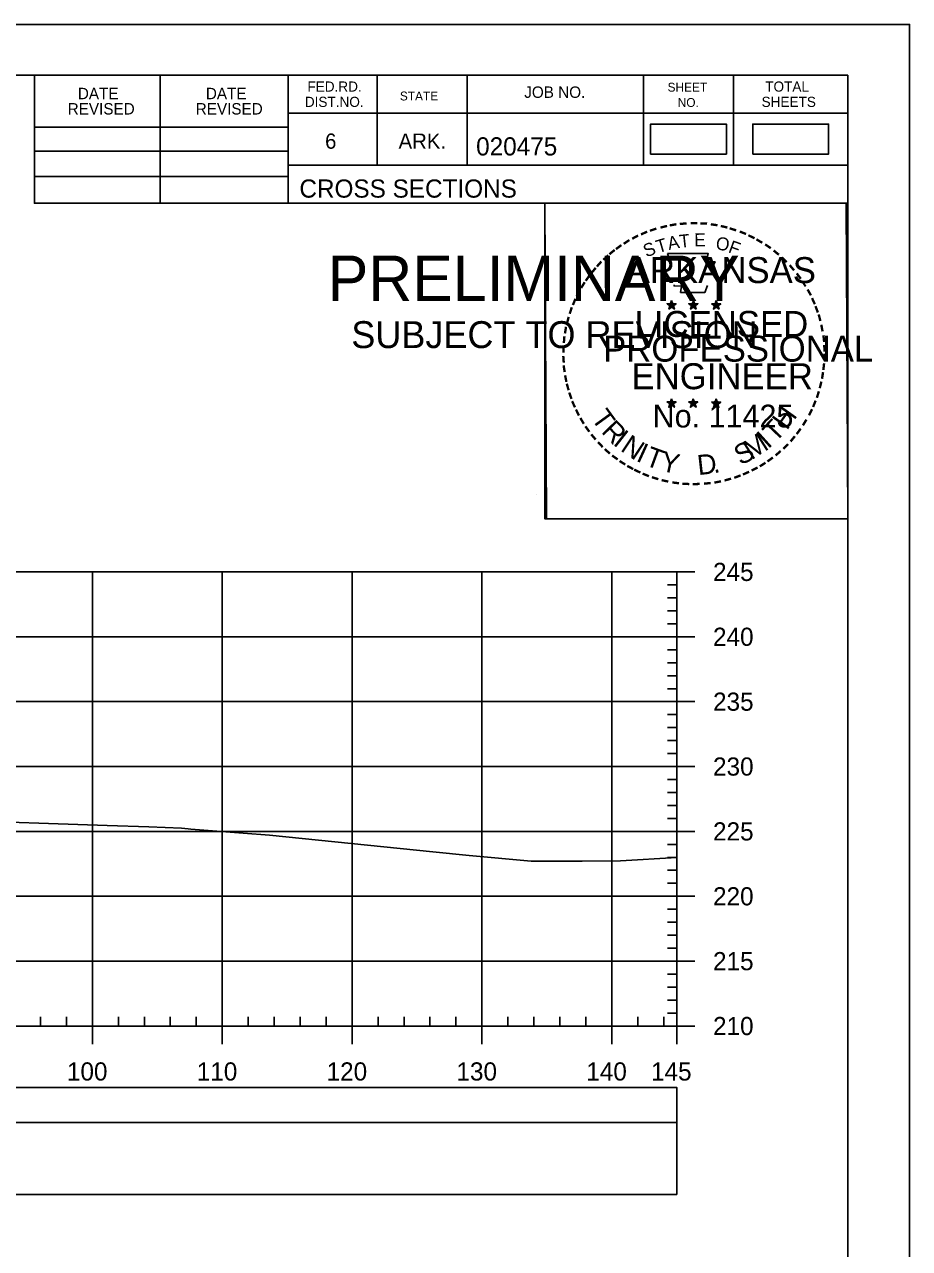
# Model space of a CAD drawing. Extents: x 1386544 to 1388153, y 379785 to 390999.
# Drawn here: x 1387472.7 to 1387540.9, y 380117.1 to 380211.5 of the extents above; entities that cross this region are included whole.
import ezdxf

# ---------------------------------------------------------------- set-up
doc = ezdxf.new("R2010")
doc.units = 0
for name, color, linetype in [('R_Axis', 7, 'Continuous'), ('R_Axis Annot', 7, 'Continuous'), ('R_Border', 7, 'Continuous'), ('R_Border PE', 7, 'Continuous'), ('R_Border Prem', 7, 'Continuous'), ('R_Exist Surface', 7, 'Continuous'), ('R_Grid', 7, 'Continuous'), ('R_No Plot', 7, 'Continuous'), ('S_SHOULDER', 7, 'Continuous')]:
    doc.layers.add(name, color=color, linetype=linetype)

msp = doc.modelspace()

# ---------------------------------------------------------------- linework, layer by layer
at = {"layer": 'R_Axis'}
for p, q in [((1387522.953, 380134.285), (1387522.953, 380169.285)), ((1387524.353, 380169.285), (1387522.953, 380169.285)), ((1387522.953, 380168.285), (1387522.253, 380168.285)), ((1387522.953, 380167.285), (1387522.253, 380167.285)), ((1387522.953, 380166.285), (1387522.253, 380166.285)), ((1387522.953, 380165.285), (1387522.253, 380165.285)), ((1387524.353, 380164.285), (1387522.953, 380164.285)), ((1387522.953, 380163.285), (1387522.253, 380163.285)), ((1387522.953, 380162.285), (1387522.253, 380162.285)), ((1387522.953, 380161.285), (1387522.253, 380161.285)), ((1387522.953, 380160.285), (1387522.253, 380160.285)), ((1387524.353, 380159.285), (1387522.953, 380159.285)), ((1387522.953, 380158.285), (1387522.253, 380158.285)), ((1387522.953, 380157.285), (1387522.253, 380157.285)), ((1387522.953, 380156.285), (1387522.253, 380156.285)), ((1387522.953, 380155.285), (1387522.253, 380155.285)), ((1387524.353, 380154.285), (1387522.953, 380154.285)), ((1387522.953, 380153.285), (1387522.253, 380153.285)), ((1387522.953, 380152.285), (1387522.253, 380152.285)), ((1387522.953, 380151.285), (1387522.253, 380151.285)), ((1387522.953, 380150.285), (1387522.253, 380150.285)), ((1387524.353, 380149.285), (1387522.953, 380149.285)), ((1387522.953, 380148.285), (1387522.253, 380148.285)), ((1387522.953, 380147.285), (1387522.253, 380147.285)), ((1387522.953, 380146.285), (1387522.253, 380146.285)), ((1387522.953, 380145.285), (1387522.253, 380145.285)), ((1387524.353, 380144.285), (1387522.953, 380144.285)), ((1387522.953, 380143.285), (1387522.253, 380143.285)), ((1387522.953, 380142.285), (1387522.253, 380142.285)), ((1387522.953, 380141.285), (1387522.253, 380141.285)), ((1387522.953, 380140.285), (1387522.253, 380140.285)), ((1387524.353, 380139.285), (1387522.953, 380139.285)), ((1387522.953, 380138.285), (1387522.253, 380138.285)), ((1387522.953, 380137.285), (1387522.253, 380137.285)), ((1387522.953, 380136.285), (1387522.253, 380136.285)), ((1387473.953, 380134.285), (1387473.953, 380134.985)), ((1387475.953, 380134.285), (1387475.953, 380134.985)), ((1387479.953, 380134.285), (1387479.953, 380134.985)), ((1387481.953, 380134.285), (1387481.953, 380134.985)), ((1387483.953, 380134.285), (1387483.953, 380134.985)), ((1387485.953, 380134.285), (1387485.953, 380134.985)), ((1387489.953, 380134.285), (1387489.953, 380134.985)), ((1387491.953, 380134.285), (1387491.953, 380134.985)), ((1387493.953, 380134.285), (1387493.953, 380134.985)), ((1387495.953, 380134.285), (1387495.953, 380134.985)), ((1387499.953, 380134.285), (1387499.953, 380134.985)), ((1387501.953, 380134.285), (1387501.953, 380134.985)), ((1387503.953, 380134.285), (1387503.953, 380134.985)), ((1387505.953, 380134.285), (1387505.953, 380134.985)), ((1387509.953, 380134.285), (1387509.953, 380134.985)), ((1387511.953, 380134.285), (1387511.953, 380134.985)), ((1387513.953, 380134.285), (1387513.953, 380134.985)), ((1387515.953, 380134.285), (1387515.953, 380134.985)), ((1387519.953, 380134.285), (1387519.953, 380134.985)), ((1387521.953, 380134.285), (1387521.953, 380134.985)), ((1387522.953, 380135.285), (1387522.253, 380135.285)), ((1387232.953, 380134.285), (1387522.953, 380134.285)), ((1387477.953, 380132.885), (1387477.953, 380134.285)), ((1387487.953, 380132.885), (1387487.953, 380134.285)), ((1387497.953, 380132.885), (1387497.953, 380134.285)), ((1387507.953, 380132.885), (1387507.953, 380134.285)), ((1387517.953, 380132.885), (1387517.953, 380134.285)), ((1387522.953, 380132.885), (1387522.953, 380134.285)), ((1387524.353, 380134.285), (1387522.953, 380134.285))]:
    msp.add_line(p, q, dxfattribs=at)
at = {"layer": 'R_Axis Annot'}
for points in [[(1387451.973, 380126.841), (1387522.953, 380126.841), (1387522.953, 380129.549), (1387451.973, 380129.549)], [(1387451.973, 380121.313), (1387522.953, 380121.313), (1387522.953, 380126.841), (1387451.973, 380126.841)]]:
    msp.add_lwpolyline(points, close=True, dxfattribs=at)
at = {"layer": 'R_Border'}
for p, q in [((1387219.953, 380207.578), (1387536.133, 380207.578)), ((1387473.493, 380197.698), (1387473.493, 380207.578)), ((1387483.173, 380197.698), (1387483.173, 380207.578)), ((1387493.033, 380207.578), (1387493.033, 380197.698)), ((1387499.873, 380207.578), (1387499.873, 380200.638)), ((1387506.813, 380207.578), (1387506.813, 380200.638)), ((1387520.393, 380207.578), (1387520.393, 380200.638)), ((1387527.333, 380207.578), (1387527.333, 380200.638)), ((1387536.133, 380002.118), (1387536.133, 380207.578)), ((1387536.133, 380204.638), (1387493.033, 380204.638)), ((1387536.133, 380204.658), (1387536.133, 380204.658)), ((1387473.493, 380203.558), (1387493.033, 380203.558)), ((1387473.493, 380201.698), (1387493.033, 380201.698)), ((1387536.133, 380200.638), (1387493.033, 380200.638)), ((1387495.993, 380200.638), (1387536.133, 380200.638)), ((1387473.493, 380199.758), (1387493.033, 380199.758)), ((1387536.133, 380197.698), (1387473.493, 380197.698))]:
    msp.add_line(p, q, dxfattribs=at)
at = {"layer": 'R_Border PE'}
for p, q in [((1387522.566, 380190.207), (1387522.525, 380189.955)), ((1387522.566, 380189.842), (1387522.566, 380190.207)), ((1387522.566, 380190.207), (1387522.615, 380189.957)), ((1387524.236, 380190.207), (1387524.195, 380189.955)), ((1387524.236, 380189.842), (1387524.236, 380190.207)), ((1387524.236, 380190.207), (1387524.285, 380189.957)), ((1387526, 380190.195), (1387525.959, 380189.943)), ((1387526, 380189.83), (1387526, 380190.195)), ((1387526, 380190.195), (1387526.049, 380189.945)), ((1387522.217, 380189.953), (1387522.566, 380189.842)), ((1387522.217, 380189.953), (1387522.47, 380189.908)), ((1387522.217, 380189.953), (1387522.454, 380189.831)), ((1387522.35, 380189.545), (1387522.566, 380189.842)), ((1387522.35, 380189.545), (1387522.476, 380189.789)), ((1387522.35, 380189.545), (1387522.564, 380189.762)), ((1387522.779, 380189.545), (1387522.564, 380189.759)), ((1387522.913, 380189.953), (1387522.566, 380189.842)), ((1387522.779, 380189.545), (1387522.566, 380189.842)), ((1387522.913, 380189.953), (1387522.627, 380189.904)), ((1387522.779, 380189.545), (1387522.642, 380189.836)), ((1387522.913, 380189.953), (1387522.709, 380189.851)), ((1387523.887, 380189.953), (1387524.236, 380189.842)), ((1387523.887, 380189.953), (1387524.14, 380189.908)), ((1387523.887, 380189.953), (1387524.124, 380189.831)), ((1387524.02, 380189.545), (1387524.236, 380189.842)), ((1387524.02, 380189.545), (1387524.146, 380189.789)), ((1387524.02, 380189.545), (1387524.234, 380189.762)), ((1387524.449, 380189.545), (1387524.234, 380189.759)), ((1387524.583, 380189.953), (1387524.236, 380189.842)), ((1387524.449, 380189.545), (1387524.236, 380189.842)), ((1387524.583, 380189.953), (1387524.297, 380189.904)), ((1387524.449, 380189.545), (1387524.312, 380189.836)), ((1387524.583, 380189.953), (1387524.379, 380189.851)), ((1387525.651, 380189.941), (1387526, 380189.83)), ((1387525.651, 380189.941), (1387525.904, 380189.896)), ((1387525.651, 380189.941), (1387525.888, 380189.819)), ((1387525.784, 380189.533), (1387526, 380189.83)), ((1387525.784, 380189.533), (1387525.91, 380189.777)), ((1387525.784, 380189.533), (1387525.998, 380189.75)), ((1387526.213, 380189.533), (1387525.998, 380189.747)), ((1387526.347, 380189.941), (1387526, 380189.83)), ((1387526.213, 380189.533), (1387526, 380189.83)), ((1387526.347, 380189.941), (1387526.061, 380189.892)), ((1387526.213, 380189.533), (1387526.076, 380189.824)), ((1387526.347, 380189.941), (1387526.143, 380189.839)), ((1387522.562, 380182.634), (1387522.521, 380182.382)), ((1387522.562, 380182.269), (1387522.562, 380182.634)), ((1387522.562, 380182.634), (1387522.611, 380182.384)), ((1387524.231, 380182.634), (1387524.19, 380182.382)), ((1387524.231, 380182.269), (1387524.231, 380182.634)), ((1387524.231, 380182.634), (1387524.28, 380182.384)), ((1387525.998, 380182.624), (1387525.957, 380182.372)), ((1387525.998, 380182.259), (1387525.998, 380182.624)), ((1387525.998, 380182.624), (1387526.047, 380182.374)), ((1387522.213, 380182.38), (1387522.562, 380182.269)), ((1387522.213, 380182.38), (1387522.466, 380182.335)), ((1387522.213, 380182.38), (1387522.45, 380182.258)), ((1387522.346, 380181.972), (1387522.562, 380182.269)), ((1387522.346, 380181.972), (1387522.472, 380182.216)), ((1387522.346, 380181.972), (1387522.56, 380182.189)), ((1387522.775, 380181.972), (1387522.56, 380182.186)), ((1387522.909, 380182.38), (1387522.562, 380182.269)), ((1387522.775, 380181.972), (1387522.562, 380182.269)), ((1387522.909, 380182.38), (1387522.623, 380182.331)), ((1387522.775, 380181.972), (1387522.638, 380182.263)), ((1387522.909, 380182.38), (1387522.705, 380182.278)), ((1387523.882, 380182.38), (1387524.231, 380182.269)), ((1387523.882, 380182.38), (1387524.135, 380182.335)), ((1387523.882, 380182.38), (1387524.119, 380182.258)), ((1387524.015, 380181.972), (1387524.231, 380182.269)), ((1387524.015, 380181.972), (1387524.141, 380182.216)), ((1387524.015, 380181.972), (1387524.229, 380182.189)), ((1387524.444, 380181.972), (1387524.229, 380182.186)), ((1387524.578, 380182.38), (1387524.231, 380182.269)), ((1387524.444, 380181.972), (1387524.231, 380182.269)), ((1387524.578, 380182.38), (1387524.292, 380182.331)), ((1387524.444, 380181.972), (1387524.307, 380182.263)), ((1387524.578, 380182.38), (1387524.374, 380182.278)), ((1387525.649, 380182.37), (1387525.998, 380182.259)), ((1387525.649, 380182.37), (1387525.902, 380182.325)), ((1387525.649, 380182.37), (1387525.886, 380182.248)), ((1387525.782, 380181.962), (1387525.998, 380182.259)), ((1387525.782, 380181.962), (1387525.908, 380182.206)), ((1387525.782, 380181.962), (1387525.996, 380182.179)), ((1387526.211, 380181.962), (1387525.996, 380182.176)), ((1387526.345, 380182.37), (1387525.998, 380182.259)), ((1387526.211, 380181.962), (1387525.998, 380182.259)), ((1387526.345, 380182.37), (1387526.059, 380182.321)), ((1387526.211, 380181.962), (1387526.074, 380182.253)), ((1387526.345, 380182.37), (1387526.141, 380182.268))]:
    msp.add_line(p, q, dxfattribs=at)
for points in [[(1387522.258, 380193.831), (1387522.527, 380193.004)], [(1387525.769, 380192.909), (1387525.911, 380193.193), (1387525.226, 380193.169), (1387525.374, 380193.831), (1387522.258, 380193.831)], [(1387522.75, 380191.408), (1387522.75, 380191.321), (1387523.313, 380191.302), (1387523.259, 380190.829), (1387525.129, 380190.829), (1387525.33, 380191.365)], [(1387522.566, 380190.207), (1387522.779, 380189.545), (1387522.217, 380189.953), (1387522.913, 380189.953), (1387522.35, 380189.545), (1387522.566, 380190.207)], [(1387524.236, 380190.207), (1387524.449, 380189.545), (1387523.887, 380189.953), (1387524.583, 380189.953), (1387524.02, 380189.545), (1387524.236, 380190.207)], [(1387526, 380190.195), (1387526.213, 380189.533), (1387525.651, 380189.941), (1387526.347, 380189.941), (1387525.784, 380189.533), (1387526, 380190.195)], [(1387522.562, 380182.634), (1387522.775, 380181.972), (1387522.213, 380182.38), (1387522.909, 380182.38), (1387522.346, 380181.972), (1387522.562, 380182.634)], [(1387524.231, 380182.634), (1387524.444, 380181.972), (1387523.882, 380182.38), (1387524.578, 380182.38), (1387524.015, 380181.972), (1387524.231, 380182.634)], [(1387525.998, 380182.624), (1387526.211, 380181.962), (1387525.649, 380182.37), (1387526.345, 380182.37), (1387525.782, 380181.962), (1387525.998, 380182.624)]]:
    msp.add_lwpolyline(points, dxfattribs=at)
for centre, radius in [((1387522.565, 380189.841), 0.172), ((1387522.565, 380189.841), 0.145), ((1387522.565, 380189.841), 0.116), ((1387522.565, 380189.841), 0.0991), ((1387522.565, 380189.841), 0.0747), ((1387522.565, 380189.841), 0.0495), ((1387522.565, 380189.841), 0.0296), ((1387524.235, 380189.841), 0.172), ((1387524.235, 380189.841), 0.145), ((1387524.235, 380189.841), 0.116), ((1387524.235, 380189.841), 0.0991), ((1387524.235, 380189.841), 0.0747), ((1387524.235, 380189.841), 0.0495), ((1387524.235, 380189.841), 0.0296), ((1387525.999, 380189.829), 0.172), ((1387525.999, 380189.829), 0.145), ((1387525.999, 380189.829), 0.116), ((1387525.999, 380189.829), 0.0991), ((1387525.999, 380189.829), 0.0747), ((1387525.999, 380189.829), 0.0495), ((1387525.999, 380189.829), 0.0296), ((1387522.561, 380182.268), 0.172), ((1387522.561, 380182.268), 0.145), ((1387522.561, 380182.268), 0.116), ((1387522.561, 380182.268), 0.0991), ((1387522.561, 380182.268), 0.0747), ((1387522.561, 380182.268), 0.0495), ((1387522.561, 380182.268), 0.0296), ((1387524.23, 380182.268), 0.172), ((1387524.23, 380182.268), 0.145), ((1387524.23, 380182.268), 0.116), ((1387524.23, 380182.268), 0.0991), ((1387524.23, 380182.268), 0.0747), ((1387524.23, 380182.268), 0.0495), ((1387524.23, 380182.268), 0.0296), ((1387525.997, 380182.258), 0.172), ((1387525.997, 380182.258), 0.145), ((1387525.997, 380182.258), 0.116), ((1387525.997, 380182.258), 0.0991), ((1387525.997, 380182.258), 0.0747), ((1387525.997, 380182.258), 0.0495), ((1387525.997, 380182.258), 0.0296)]:
    msp.add_circle(centre, radius, dxfattribs=at)
at = {"layer": 'R_Exist Surface'}
msp.add_lwpolyline([(1387467.036, 380150.158), (1387479.096, 380149.737), (1387482.296, 380149.628), (1387484.806, 380149.543), (1387485.337, 380149.487), (1387485.528, 380149.462), (1387489.571, 380149.143), (1387491.58, 380149.007), (1387504.176, 380147.706), (1387506.96, 380147.427), (1387511.746, 380146.984), (1387515.664, 380146.994), (1387518.617, 380147.012), (1387522.953, 380147.281)], dxfattribs=at)
at = {"layer": 'R_Grid'}
for p, q in [((1387232.953, 380169.285), (1387522.953, 380169.285)), ((1387477.953, 380134.285), (1387477.953, 380169.285)), ((1387487.953, 380134.285), (1387487.953, 380169.285)), ((1387497.953, 380134.285), (1387497.953, 380169.285)), ((1387507.953, 380134.285), (1387507.953, 380169.285)), ((1387517.953, 380134.285), (1387517.953, 380169.285)), ((1387522.953, 380134.285), (1387522.953, 380169.285)), ((1387232.953, 380164.285), (1387522.953, 380164.285)), ((1387232.953, 380159.285), (1387522.953, 380159.285)), ((1387232.953, 380154.285), (1387522.953, 380154.285)), ((1387232.953, 380149.285), (1387522.953, 380149.285)), ((1387232.953, 380144.285), (1387522.953, 380144.285)), ((1387232.953, 380139.285), (1387522.953, 380139.285)), ((1387232.953, 380134.285), (1387522.953, 380134.285))]:
    msp.add_line(p, q, dxfattribs=at)
at = {"layer": 'R_No Plot'}
for p, q in [((1387207.552, 380211.473), (1387540.885, 380211.473)), ((1387512.167, 380175.242), (1387512.167, 380175.242))]:
    msp.add_line(p, q, dxfattribs=at)
for points in [[(1387207.545, 380211.473), (1387540.885, 380211.473), (1387540.885, 379998.135), (1387207.545, 379998.135)], [(1387453.873, 380207.578), (1387473.493, 380207.578), (1387473.493, 380197.698), (1387489.605, 380197.698), (1387512.804, 380197.698), (1387512.804, 380173.365), (1387536.133, 380173.365), (1387536.133, 380002.118), (1387219.953, 380002.118), (1387219.953, 380207.578)], [(1387512.804, 380197.698), (1387536.012, 380197.698), (1387536.133, 380173.365), (1387512.925, 380173.365)]]:
    msp.add_lwpolyline(points, close=True, dxfattribs=at)
at = {"layer": 'S_SHOULDER'}
for points in [[(1387520.946, 380201.483), (1387526.779, 380201.483), (1387526.779, 380203.793), (1387520.946, 380203.793)], [(1387528.816, 380201.483), (1387534.649, 380201.483), (1387534.649, 380203.793), (1387528.816, 380203.793)]]:
    msp.add_lwpolyline(points, close=True, dxfattribs=at)

# ---------------------------------------------------------------- texts
at = {"layer": 'R_Axis Annot'}
for s, p in [('245', (1387525.753, 380168.585)), ('240', (1387525.753, 380163.585)), ('235', (1387525.753, 380158.585)), ('230', (1387525.753, 380153.585)), ('225', (1387525.753, 380148.585)), ('220', (1387525.753, 380143.585)), ('215', (1387525.753, 380138.585)), ('210', (1387525.753, 380133.585)), ('100', (1387475.991, 380130.085)), ('110', (1387485.991, 380130.085)), ('120', (1387495.991, 380130.085)), ('130', (1387505.991, 380130.085)), ('140', (1387515.991, 380130.085)), ('145', (1387520.978, 380130.085))]:
    msp.add_text(s, height=1.4, dxfattribs=at).set_placement(p)
at = {"layer": 'R_Border'}
for s, height, p in [('FED.RD.', 0.7819, (1387494.513, 380206.298)), ('TOTAL', 0.7819, (1387529.773, 380206.298)), ('DATE', 0.8792, (1387476.83, 380205.714)), ('DATE', 0.8792, (1387486.69, 380205.714)), ('STATE', 0.684, (1387501.633, 380205.618)), ('JOB NO.', 0.8792, (1387511.213, 380205.818)), ('SHEET', 0.684, (1387522.253, 380206.298)), ('REVISED', 0.8792, (1387476.05, 380204.534)), ('REVISED', 0.8792, (1387485.91, 380204.534)), ('DIST.NO.', 0.7819, (1387494.313, 380205.118)), ('NO.', 0.684, (1387523.033, 380205.118)), ('SHEETS', 0.7819, (1387529.493, 380205.118)), ('6', 1.172, (1387495.873, 380201.898)), ('ARK.', 1.1723, (1387501.533, 380201.898)), ('020475', 1.4, (1387507.508, 380201.378)), ('CROSS SECTIONS', 1.4, (1387493.896, 380198.128))]:
    msp.add_text(s, height=height, rotation=360, dxfattribs=at).set_placement(p)
at = {"layer": 'R_Border PE'}
for s, height, rotation, p in [('-', 1.6, 19.17608, (1387521.006, 380194.958)), ('-', 1.6, 13.63015, (1387521.756, 380195.199)), ('-', 1.6, 10.21935, (1387522.434, 380195.361)), ('-', 1.6, 5.89682, (1387523.163, 380195.471)), ('-', 1.6, 0.18623, (1387523.935, 380195.543)), ('-', 1.6, 357.74304, (1387524.658, 380195.53)), ('-', 1.6, 352.16172, (1387525.402, 380195.474)), ('-', 1.6, 347.20489, (1387526.121, 380195.36)), ('-', 1.6, 342.3362, (1387526.756, 380195.205)), ('-', 1.6, 34.06357, (1387519.142, 380194.002)), ('-', 1.6, 28.79182, (1387519.739, 380194.372)), ('-', 1.6, 24.30721, (1387520.372, 380194.689)), ('T', 1, 16.4036, (1387521.527, 380193.84)), ('A', 1, 11.21318, (1387522.353, 380194.091)), ('T', 1, 6.02276, (1387523.202, 380194.257)), ('E', 1, 0.83234, (1387524.307, 380194.367)), ('O', 1, 350.4515, (1387525.911, 380194.157)), ('F', 1, 340.07066, (1387526.865, 380193.929)), ('-', 1.6, 337.85509, (1387527.491, 380194.982)), ('-', 1.6, 334.12109, (1387528.122, 380194.711)), ('-', 1.6, 329.64089, (1387528.701, 380194.428)), ('-', 1.6, 38.95066, (1387518.088, 380193.229)), ('-', 1.6, 36.23174, (1387518.564, 380193.607)), ('S', 1, 21.59401, (1387520.613, 380193.509)), ('-', 1.6, 325.86266, (1387529.344, 380194.067)), ('-', 1.6, 320.52971, (1387529.954, 380193.641)), ('-', 1.6, 48.42305, (1387517.207, 380192.334)), ('-', 1.6, 42.96224, (1387517.655, 380192.812)), ('ARKANSAS', 2, 360, (1387519.111, 380191.543)), ('-', 1.6, 315.57859, (1387530.553, 380193.153)), ('-', 1.6, 309.87973, (1387531.122, 380192.603)), ('-', 1.6, 54.23247, (1387516.391, 380191.281)), ('-', 1.6, 50.61417, (1387516.804, 380191.848)), ('-', 1.6, 306.65218, (1387531.647, 380192.001)), ('-', 1.6, 58.07063, (1387516.066, 380190.754)), ('-', 1.4, 303.67529, (1387532.133, 380191.433)), ('-', 1.6, 299.66835, (1387532.452, 380190.826)), ('-', 1.6, 67.77427, (1387515.494, 380189.529)), ('-', 1.6, 62.87135, (1387515.753, 380190.14)), ('-', 1.6, 294.66279, (1387532.776, 380190.214)), ('-', 1.6, 72.39447, (1387515.275, 380188.899)), ('LICENSED', 2, 360, (1387519.709, 380187.394)), ('DWB', 0.01, 360, (1387522.554, 380189.837)), ('DWB', 0.01, 360, (1387524.223, 380189.837)), ('DWB', 0.01, 360, (1387525.988, 380189.826)), ('-', 1.6, 290.57283, (1387533.033, 380189.637)), ('-', 1.6, 285.12326, (1387533.267, 380189.057)), ('-', 1.6, 81.20126, (1387514.946, 380187.472)), ('-', 1.6, 75.46096, (1387515.078, 380188.185)), ('-', 1.6, 280.54934, (1387533.467, 380188.315)), ('-', 1.6, 85.18634, (1387514.87, 380186.781)), ('PROFESSIONAL', 2, 360, (1387517.285, 380185.49)), ('-', 1.6, 276.59616, (1387533.629, 380187.547)), ('-', 1.6, 89.06224, (1387514.845, 380186.08)), ('-', 1.6, 274.33011, (1387533.689, 380186.825)), ('-', 1.6, 94.19588, (1387514.88, 380185.355)), ('ENGINEER', 2, 360, (1387519.472, 380183.365)), ('-', 1.6, 263.5172, (1387533.704, 380185.527)), ('-', 1.6, 269.94067, (1387533.723, 380186.193)), ('-', 1.6, 98.94793, (1387514.952, 380184.688)), ('-', 1.6, 101.71495, (1387515.087, 380183.955)), ('-', 1.6, 260.99529, (1387533.633, 380184.873)), ('-', 1.6, 105.45785, (1387515.249, 380183.36)), ('-', 1.6, 255.7626, (1387533.523, 380184.195)), ('-', 1.6, 109.08742, (1387515.464, 380182.729)), ('-', 1.6, 252.86809, (1387533.342, 380183.475)), ('-', 1.6, 114.06432, (1387515.718, 380182.133)), ('-', 1.6, 115.72885, (1387516.023, 380181.515)), ('T', 1.54, 306.04056, (1387516.322, 380181.107)), ('No. 11425', 1.757, 360, (1387521.1, 380180.414)), ('DWB', 0.01, 360, (1387522.55, 380182.264)), ('DWB', 0.01, 360, (1387524.219, 380182.264)), ('DWB', 0.01, 360, (1387525.986, 380182.254)), ('H', 1.54, 54.60883, (1387531.442, 380180.142)), ('-', 1.6, 244.61971, (1387532.857, 380182.173)), ('-', 1.6, 247.88866, (1387533.119, 380182.802)), ('-', 1.6, 120.44712, (1387516.38, 380180.929)), ('R', 1.54, 314.00497, (1387517.085, 380180.06)), ('T', 1.54, 46.64442, (1387530.553, 380179.2)), ('-', 1.6, 239.07125, (1387532.463, 380181.421)), ('-', 1.6, 125.89344, (1387516.783, 380180.368)), ('-', 1.6, 130.71812, (1387517.245, 380179.816)), ('I', 1.54, 321.96938, (1387517.985, 380179.127)), ('N', 1.54, 326.50021, (1387518.552, 380178.656)), ('M', 1.54, 32.65632, (1387528.707, 380177.875)), ('I', 1.54, 42.11359, (1387529.991, 380178.722)), ('-', 1.6, 231.25377, (1387531.631, 380180.202)), ('-', 1.6, 233.84524, (1387532.061, 380180.768)), ('-', 1.6, 134.22381, (1387517.762, 380179.271)), ('-', 1.6, 138.93382, (1387518.287, 380178.807)), ('I', 1.54, 335.36034, (1387519.76, 380177.87)), ('T', 1.54, 339.89117, (1387520.421, 380177.543)), ('S', 1.54, 26.9312, (1387527.868, 380177.469)), ('-', 1.6, 225.76533, (1387531.152, 380179.638)), ('-', 1.6, 144.64634, (1387518.843, 380178.401)), ('-', 1.6, 148.08978, (1387519.404, 380178.03)), ('Y', 1.54, 347.85558, (1387521.638, 380177.097)), ('D', 1.54, 6.39691, (1387524.623, 380176.739)), ('-', 1.6, 215.73633, (1387530.081, 380178.657)), ('-', 1.6, 221.08509, (1387530.63, 380179.129)), ('-', 1.6, 151.57039, (1387519.983, 380177.705)), ('-', 1.6, 154.60019, (1387520.505, 380177.458)), ('-', 1.6, 158.56121, (1387521.129, 380177.204)), ('.', 1.54, 13.76417, (1387525.815, 380176.866)), ('-', 1.6, 204.25161, (1387528.365, 380177.605)), ('-', 1.6, 207.35684, (1387528.989, 380177.924)), ('-', 1.6, 212.24909, (1387529.547, 380178.27)), ('-', 1.6, 162.79826, (1387521.816, 380176.991)), ('-', 1.6, 167.55551, (1387522.531, 380176.827)), ('-', 1.6, 173.11546, (1387523.303, 380176.717)), ('-', 1.6, 176.51827, (1387524.051, 380176.664)), ('-', 1.6, 181.59176, (1387524.795, 380176.683)), ('-', 1.6, 185.81666, (1387525.604, 380176.759)), ('-', 1.6, 191.28576, (1387526.34, 380176.891)), ('-', 1.6, 195.47429, (1387527.069, 380177.09)), ('-', 1.6, 200.71842, (1387527.746, 380177.332))]:
    msp.add_text(s, height=height, rotation=rotation, dxfattribs=at).set_placement(p)
at = {"layer": 'R_Border Prem'}
for s, height, p in [('PRELIMINARY', 3.5, (1387496.084, 380190.161)), ('DWB', 0.01, (1387496.83, 380192.01)), ('SUBJECT TO REVISION', 2.07511, (1387497.893, 380186.532))]:
    msp.add_text(s, height=height, rotation=360, dxfattribs=at).set_placement(p)

doc.saveas('drawing.dxf')
